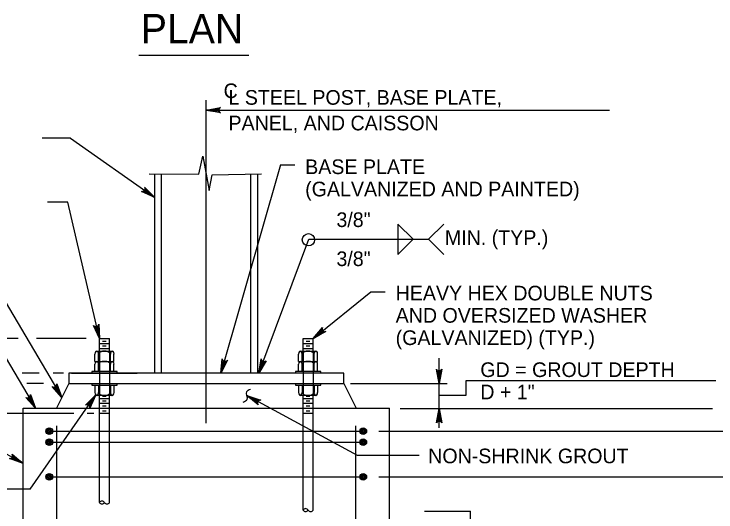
# Model space of a CAD drawing. Extents: x 3475 to 6558, y -3780 to 1166.
# Drawn here: x 3917 to 4064.1, y -275.9 to -171.5 of the extents above; entities that cross this region are included whole.
import ezdxf

# ---------------------------------------------------------------- set-up
doc = ezdxf.new("R2010")
doc.units = 0
doc.layers.add('1', color=7, linetype='Continuous')

msp = doc.modelspace()

# ---------------------------------------------------------------- linework, layer by layer
at = {"layer": '1'}
for p, q in [((3943.12, -180.12), (3966.18, -180.12)), ((3957.26, -257.25), (3957.26, -189.52)), ((3957.26, -191.62), (4041.73, -191.62)), ((3928.84, -197.53), (3922.89, -197.53)), ((3928.84, -197.53), (3946.46, -209.91)), ((3972.79, -203.07), (3960.32, -246.79)), ((3972.79, -203.07), (3975.83, -203.07)), ((3946.46, -246.79), (3946.46, -204.96)), ((3947.9, -246.79), (3947.9, -204.98)), ((3966.62, -246.79), (3966.62, -205.03)), ((3968.06, -246.79), (3968.06, -204.99)), ((3928.23, -210.89), (3924.02, -210.89)), ((3934.86, -239.53), (3928.23, -210.89)), ((3997.42, -215.51), (3997.42, -221.9)), ((4000.62, -218.71), (3997.42, -215.51)), ((4003.81, -218.71), (4007, -215.51)), ((3968.25, -246.79), (3978.72, -218.71)), ((3978.72, -218.71), (4003.81, -218.71)), ((4000.62, -218.71), (3997.42, -221.9)), ((4003.81, -218.71), (4007, -221.9)), ((3908.4, -220.41), (3926.96, -251.87)), ((3907.22, -230.03), (3921.44, -254.13)), ((3979.66, -239.53), (3991.72, -229.69)), ((3991.72, -229.69), (3994.75, -229.69)), ((3917.81, -239.53), (3914.33, -239.53)), ((3932.09, -239.53), (3921.65, -239.53)), ((3934.86, -239.53), (3936.99, -239.53)), ((3934.86, -242.18), (3934.86, -239.53)), ((3936.99, -242.18), (3936.99, -239.53)), ((3977.53, -239.53), (3979.66, -239.53)), ((3977.53, -242.18), (3977.53, -239.53)), ((3979.66, -242.18), (3979.66, -239.53)), ((3934.86, -240.55), (3936.99, -240.55)), ((3935.54, -240.04), (3936.31, -240.04)), ((3935.54, -241.06), (3936.31, -241.06)), ((3977.53, -240.55), (3979.66, -240.55)), ((3978.21, -240.04), (3978.98, -240.04)), ((3978.21, -241.06), (3978.98, -241.06)), ((3934.31, -242.18), (3937.54, -242.18)), ((3934.86, -241.57), (3936.99, -241.57)), ((3934.86, -242.18), (3934.86, -251.43)), ((3935.54, -242.09), (3936.31, -242.09)), ((3936.99, -242.18), (3936.99, -251.43)), ((3976.98, -242.18), (3980.21, -242.18)), ((3977.53, -241.57), (3979.66, -241.57)), ((3977.53, -242.18), (3977.53, -251.43)), ((3978.21, -242.09), (3978.98, -242.09)), ((3979.66, -242.18), (3979.66, -251.43)), ((3933.92, -244.31), (3933.92, -242.77)), ((3934.69, -244.31), (3934.69, -242.77)), ((3937.16, -244.31), (3937.16, -242.77)), ((3937.92, -244.31), (3937.92, -242.77)), ((3976.59, -244.31), (3976.59, -242.77)), ((3977.36, -244.31), (3977.36, -242.77)), ((3979.83, -244.31), (3979.83, -242.77)), ((3980.59, -244.31), (3980.59, -242.77)), ((4006.03, -258.22), (4006.03, -243.66)), ((3933.92, -244.31), (3937.92, -244.31)), ((3933.92, -246.44), (3933.92, -244.91)), ((3934.31, -244.31), (3937.54, -244.31)), ((3934.69, -246.44), (3934.69, -244.91)), ((3937.16, -246.44), (3937.16, -244.91)), ((3937.92, -246.44), (3937.92, -244.91)), ((3976.59, -244.31), (3980.59, -244.31)), ((3976.59, -246.44), (3976.59, -244.91)), ((3976.98, -244.31), (3980.21, -244.31)), ((3977.36, -246.44), (3977.36, -244.91)), ((3979.83, -246.44), (3979.83, -244.91)), ((3980.59, -246.44), (3980.59, -244.91)), ((3922.23, -246.79), (3918.65, -246.79)), ((3927.31, -246.79), (3925.21, -246.79)), ((3986.06, -246.79), (3928.46, -246.79)), ((3928.46, -246.79), (3928.46, -248.95)), ((3929.04, -246.79), (3942.81, -246.79)), ((3933.28, -246.44), (3933.28, -246.79)), ((3938.57, -246.44), (3933.28, -246.44)), ((3938.57, -246.79), (3938.57, -246.44)), ((3975.95, -246.44), (3975.95, -246.79)), ((3981.24, -246.44), (3975.95, -246.44)), ((3981.24, -246.79), (3981.24, -246.44)), ((3986.06, -248.95), (3986.06, -246.79)), ((4011.72, -248.29), (4064.01, -248.29)), ((4011.72, -251.36), (4011.72, -248.29)), ((3923.14, -248.95), (3919.66, -248.95)), ((3928.46, -248.95), (3925.87, -254.13)), ((3928.46, -248.95), (3986.06, -248.95)), ((3933.28, -248.95), (3933.28, -249.3)), ((3933.28, -249.3), (3938.57, -249.3)), ((3933.92, -249.3), (3933.92, -250.83)), ((3934.69, -249.3), (3934.69, -250.83)), ((3937.16, -249.3), (3937.16, -250.83)), ((3937.92, -249.3), (3937.92, -250.83)), ((3938.57, -249.3), (3938.57, -248.95)), ((3975.95, -248.95), (3975.95, -249.3)), ((3975.95, -249.3), (3981.24, -249.3)), ((3976.59, -249.3), (3976.59, -250.83)), ((3977.36, -249.3), (3977.36, -250.83)), ((3979.83, -249.3), (3979.83, -250.83)), ((3980.59, -249.3), (3980.59, -250.83)), ((3981.24, -249.3), (3981.24, -248.95)), ((3986.06, -248.95), (3988.65, -254.13)), ((3987.46, -248.95), (4007.72, -248.95)), ((3920.38, -271.13), (3934.1, -251.33)), ((3937.54, -251.43), (3934.31, -251.43)), ((3934.86, -273.88), (3934.86, -251.43)), ((3936.99, -273.88), (3936.99, -251.43)), ((3988.94, -264.07), (3965.79, -251.48)), ((3980.21, -251.43), (3976.98, -251.43)), ((3977.53, -275.47), (3977.53, -251.43)), ((3979.66, -275.47), (3979.66, -251.43)), ((4006.03, -251.36), (4011.72, -251.36)), ((3936.99, -252.15), (3934.86, -252.15)), ((3936.31, -251.64), (3935.54, -251.64)), ((3936.31, -252.66), (3935.54, -252.66)), ((3979.66, -252.15), (3977.53, -252.15)), ((3978.98, -251.64), (3978.21, -251.64)), ((3978.98, -252.66), (3978.21, -252.66)), ((3918.87, -254.13), (3934.86, -254.13)), ((3918.87, -371.81), (3918.87, -254.13)), ((3936.99, -253.17), (3934.86, -253.17)), ((3936.99, -254.2), (3934.86, -254.2)), ((3936.31, -253.68), (3935.54, -253.68)), ((3936.99, -254.13), (3977.53, -254.13)), ((3979.66, -253.17), (3977.53, -253.17)), ((3979.66, -254.2), (3977.53, -254.2)), ((3978.98, -253.68), (3978.21, -253.68)), ((3979.66, -254.13), (3995.65, -254.13)), ((3995.65, -371.81), (3995.65, -254.13)), ((3997.85, -254.2), (4063.35, -254.2)), ((3929.53, -255.22), (3895.74, -255.22)), ((3933.71, -255.22), (3932.31, -255.22)), ((3936.99, -255.22), (3934.86, -255.22)), ((3936.31, -254.71), (3935.54, -254.71)), ((3979.66, -255.22), (3977.53, -255.22)), ((3978.98, -254.71), (3978.21, -254.71)), ((3925.91, -371.81), (3925.91, -257.81)), ((3988.61, -371.81), (3988.61, -257.81)), ((3908.86, -259.99), (3918.87, -265.69)), ((3924.37, -258.93), (3990.15, -258.93)), ((3993.38, -258.93), (4101.4, -258.93)), ((3924.37, -261.24), (3990.15, -261.24)), ((4001.88, -264.07), (3988.94, -264.07)), ((3924.37, -268.53), (3990.15, -268.53)), ((3993.38, -268.53), (4101.4, -268.53)), ((3920.38, -271.13), (3897.71, -271.13)), ((4002.97, -275.74), (4012.62, -275.74)), ((4012.62, -286.74), (4012.62, -275.74))]:
    msp.add_line(p, q, dxfattribs=at)
for points in [[(3957.26, -191.62), (3960.24, -191.06), (3960.01, -191.22), (3959.89, -191.42), (3959.86, -191.62), (3959.89, -191.82), (3960.01, -192.02), (3960.24, -192.18), (3957.26, -191.62), (3960.01, -192.02), (3959.89, -191.82), (3957.26, -191.62), (3959.86, -191.62), (3959.89, -191.42), (3957.26, -191.62), (3960.01, -191.22)], [(3945.28, -204.95), (3955.73, -205.06), (3956.55, -201.26), (3957.83, -208.46), (3958.52, -205.21), (3968.86, -204.98)], [(3946.46, -209.91), (3943.69, -208.65), (3943.83, -208.66), (3943.97, -208.66), (3944.08, -208.61), (3944.19, -208.56), (3944.26, -208.49), (3944.33, -208.42), (3944.37, -208.32), (3944.42, -208.23), (3944.43, -208.12), (3944.43, -208), (3944.39, -207.87), (3944.34, -207.74), (3946.46, -209.91), (3944.39, -207.87), (3944.43, -208), (3946.46, -209.91), (3944.43, -208.12), (3944.42, -208.23), (3946.46, -209.91), (3944.37, -208.32), (3944.33, -208.42), (3946.46, -209.91), (3944.26, -208.49), (3944.19, -208.56), (3946.46, -209.91), (3944.08, -208.61), (3943.97, -208.66), (3946.46, -209.91), (3943.83, -208.66)], [(3934.86, -239.53), (3933.64, -236.75), (3933.85, -236.93), (3934.07, -237), (3934.27, -236.99), (3934.46, -236.91), (3934.63, -236.75), (3934.73, -236.49), (3934.86, -239.53), (3934.63, -236.75), (3934.46, -236.91), (3934.86, -239.53), (3934.27, -236.99), (3934.07, -237), (3934.86, -239.53), (3933.85, -236.93)], [(3979.66, -239.53), (3981.62, -237.21), (3981.54, -237.48), (3981.57, -237.71), (3981.67, -237.88), (3981.83, -238.02), (3982.05, -238.1), (3982.32, -238.07), (3979.66, -239.53), (3982.05, -238.1), (3981.83, -238.02), (3979.66, -239.53), (3981.67, -237.88), (3981.57, -237.71), (3979.66, -239.53), (3981.54, -237.48)], [(3960.32, -246.79), (3960.6, -243.77), (3960.69, -244.03), (3960.85, -244.2), (3961.03, -244.29), (3961.24, -244.31), (3961.46, -244.25), (3961.68, -244.07), (3960.32, -246.79), (3961.46, -244.25), (3961.24, -244.31), (3960.32, -246.79), (3961.03, -244.29), (3960.85, -244.2), (3960.32, -246.79), (3960.69, -244.03)], [(3968.25, -246.79), (3968.77, -243.8), (3968.84, -244.07), (3968.98, -244.25), (3969.16, -244.35), (3969.36, -244.39), (3969.59, -244.35), (3969.82, -244.19), (3968.25, -246.79), (3969.59, -244.35), (3969.36, -244.39), (3968.25, -246.79), (3969.16, -244.35), (3968.98, -244.25), (3968.25, -246.79), (3968.84, -244.07)], [(4006.03, -248.95), (4005.47, -245.97), (4005.63, -246.2), (4005.83, -246.32), (4006.03, -246.35), (4006.23, -246.32), (4006.43, -246.2), (4006.59, -245.97), (4006.03, -248.95), (4006.43, -246.2), (4006.23, -246.32), (4006.03, -248.95), (4006.03, -246.35), (4005.83, -246.32), (4006.03, -248.95), (4005.63, -246.2)], [(3926.96, -251.87), (3924.96, -249.58), (3925.22, -249.7), (3925.45, -249.7), (3925.64, -249.63), (3925.79, -249.5), (3925.9, -249.29), (3925.92, -249.01), (3926.96, -251.87), (3925.9, -249.29), (3925.79, -249.5), (3926.96, -251.87), (3925.64, -249.63), (3925.45, -249.7), (3926.96, -251.87), (3925.22, -249.7)], [(3921.44, -254.13), (3919.44, -251.85), (3919.7, -251.96), (3919.93, -251.96), (3920.12, -251.89), (3920.28, -251.76), (3920.39, -251.56), (3920.41, -251.28), (3921.44, -254.13), (3920.39, -251.56), (3920.28, -251.76), (3921.44, -254.13), (3920.12, -251.89), (3919.93, -251.96), (3921.44, -254.13), (3919.7, -251.96)], [(3934.1, -251.33), (3932.86, -254.1), (3932.86, -253.82), (3932.76, -253.61), (3932.61, -253.47), (3932.43, -253.38), (3932.2, -253.37), (3931.94, -253.46), (3934.1, -251.33), (3932.2, -253.37), (3932.43, -253.38), (3934.1, -251.33), (3932.61, -253.47), (3932.76, -253.61), (3934.1, -251.33), (3932.86, -253.82)], [(3965.79, -251.48), (3968.68, -252.41), (3968.4, -252.44), (3968.2, -252.56), (3968.07, -252.72), (3968.01, -252.91), (3968.01, -253.15), (3968.14, -253.39), (3965.79, -251.48), (3968.01, -253.15), (3968.01, -252.91), (3965.79, -251.48), (3968.07, -252.72), (3968.2, -252.56), (3965.79, -251.48), (3968.4, -252.44)], [(4006.03, -254.2), (4006.59, -257.19), (4006.43, -256.96), (4006.23, -256.84), (4006.03, -256.8), (4005.83, -256.84), (4005.63, -256.96), (4005.47, -257.19), (4006.03, -254.2), (4005.63, -256.96), (4005.83, -256.84), (4006.03, -254.2), (4006.03, -256.8), (4006.23, -256.84), (4006.03, -254.2), (4006.43, -256.96)], [(3918.87, -265.69), (3916, -264.7), (3916.28, -264.67), (3916.48, -264.56), (3916.61, -264.4), (3916.68, -264.21), (3916.67, -263.98), (3916.55, -263.73), (3918.87, -265.69), (3916.67, -263.98), (3916.68, -264.21), (3918.87, -265.69), (3916.61, -264.4), (3916.48, -264.56), (3918.87, -265.69), (3916.28, -264.67)]]:
    msp.add_lwpolyline(points, dxfattribs=at)
for centre, radius in [((3978.66, -218.81), 1.29), ((3924.37, -258.93), 0.701), ((3924.37, -258.93), 0.53), ((3924.37, -258.93), 0.379), ((3924.37, -258.93), 0.215), ((3990.15, -258.93), 0.701), ((3990.15, -258.93), 0.53), ((3990.15, -258.93), 0.379), ((3990.15, -258.93), 0.215), ((3924.37, -261.24), 0.701), ((3924.37, -261.24), 0.53), ((3924.37, -261.24), 0.379), ((3924.37, -261.24), 0.215), ((3990.15, -261.24), 0.701), ((3990.15, -261.24), 0.53), ((3990.15, -261.24), 0.379), ((3990.15, -261.24), 0.215), ((3924.37, -268.53), 0.701), ((3924.37, -268.53), 0.53), ((3924.37, -268.53), 0.379), ((3924.37, -268.53), 0.215), ((3990.15, -268.53), 0.701), ((3990.15, -268.53), 0.53), ((3990.15, -268.53), 0.379), ((3990.15, -268.53), 0.215)]:
    msp.add_circle(centre, radius, dxfattribs=at)
for centre, start, end in [((3935.39, -274.22), 32.1976, 147.8024), ((3935.39, -273.55), 212.1976, 327.8024), ((3936.46, -273.55), 212.1976, 327.8024), ((3978.06, -275.81), 32.1976, 147.8024), ((3978.06, -275.14), 212.1976, 327.8024), ((3979.13, -275.14), 212.1976, 327.8024)]:
    msp.add_arc(centre, 0.63, start, end, dxfattribs=at)
for centre, major_axis, ratio, start_param, end_param in [((3934.31, -242.77), (0, -0.597), 0.6417, 1.570796, 4.712389), ((3935.92, -242.77), (-1.23, 0), 0.483604, 3.141593, 6.283185), ((3937.54, -242.77), (0, -0.597), 0.6417, 1.570796, 4.712389), ((3976.98, -242.77), (0, -0.597), 0.6417, 1.570796, 4.712389), ((3978.59, -242.77), (-1.23, 0), 0.483604, 3.141593, 6.283185), ((3980.21, -242.77), (0, -0.597), 0.6417, 1.570796, 4.712389), ((3934.31, -244.91), (0, -0.597), 0.6417, 1.570796, 4.712389), ((3935.92, -244.91), (-1.23, 0), 0.483604, 3.141593, 6.283185), ((3937.54, -244.91), (0, -0.597), 0.6417, 1.570796, 4.712389), ((3976.98, -244.91), (0, -0.597), 0.6417, 1.570796, 4.712389), ((3978.59, -244.91), (-1.23, 0), 0.483604, 3.141593, 6.283185), ((3980.21, -244.91), (0, -0.597), 0.6417, 1.570796, 4.712389), ((3934.31, -250.83), (0, 0.597), 0.6417, 1.570796, 4.712389), ((3935.92, -250.83), (1.23, 0), 0.483604, 3.141593, 6.283185), ((3937.54, -250.83), (0, 0.597), 0.6417, 1.570796, 4.712389), ((3976.98, -250.83), (0, 0.597), 0.6417, 1.570796, 4.712389), ((3978.59, -250.83), (1.23, 0), 0.483604, 3.141593, 6.283185), ((3980.21, -250.83), (0, 0.597), 0.6417, 1.570796, 4.712389)]:
    msp.add_ellipse(centre, major_axis=major_axis, ratio=ratio, start_param=start_param, end_param=end_param, dxfattribs=at)
msp.add_spline([(3965.01, -252.83), (3965.83, -252.29), (3965.74, -250.65), (3966.51, -250.1)], degree=3, dxfattribs=at)

# ---------------------------------------------------------------- texts
for s, height, p in [('PLAN', 6.144, (3943.54, -177.61)), ('C', 3.07, (3960.89, -189.1)), ('L STEEL POST, BASE PLATE,', 3.072, (3961.91, -190.49)), ('PANEL, AND CAISSON', 3.072, (3961.91, -195.86)), ('BASE PLATE', 3.072, (3977.98, -205.03)), ('(GALVANIZED AND PAINTED)', 3.072, (3977.98, -209.7)), ('3/8"', 3.072, (3984.53, -216.13)), ('MIN. (TYP.)', 3.072, (4007.25, -219.88)), ('3/8"', 3.072, (3984.53, -224.32)), ('HEAVY HEX DOUBLE NUTS', 3.072, (3996.94, -231.52)), ('AND OVERSIZED WASHER', 3.072, (3996.94, -236.19)), ('(GALVANIZED) (TYP.)', 3.072, (3996.94, -240.87)), ('GD = GROUT DEPTH ', 3.072, (4014.68, -247.58)), ('D + 1"', 3.072, (4014.68, -252.26)), ('NON-SHRINK GROUT', 3.072, (4003.76, -265.67))]:
    msp.add_text(s, height=height, dxfattribs=at).set_placement(p)

doc.saveas('drawing.dxf')
